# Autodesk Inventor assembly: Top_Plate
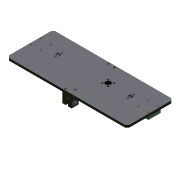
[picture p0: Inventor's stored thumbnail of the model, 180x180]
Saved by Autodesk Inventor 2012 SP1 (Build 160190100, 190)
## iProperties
Created: 2005-12
Part Number: Top_Plate
Document SubType Name: Assembly
Designer: Neil
Author: Neil
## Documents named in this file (6)
- D:\AOTC\Autodesk Inventor 2012 Essential for New Users\Autodesk Inventor 2012 Essentials - Project Files\Learning\Workspace\Sub-Assemblies\Top_Plate.iam
- D:\AOTC\Autodesk Inventor 2012 Essential for New Users\Autodesk Inventor 2012 Essentials - Project Files\Learning\Workspace\Parts\cam guide.ipt
- D:\AOTC\Autodesk Inventor 2012 Essential for New Users\Autodesk Inventor 2012 Essentials - Project Files\Learning\Workspace\Parts\AD7DE3A0-7CFF-06A5-6856-A7BB906EE278.ipt
- D:\AOTC\Autodesk Inventor 2012 Essential for New Users\Autodesk Inventor 2012 Essentials - Project Files\Learning\Workspace\Parts\TLM-2022.ipt
- D:\AOTC\Autodesk Inventor 2012 Essential for New Users\Autodesk Inventor 2012 Essentials - Project Files\Learning\Workspace\Sub-Assemblies\Pivot.iam
- D:\AOTC\Autodesk Inventor 2012 Essential for New Users\Autodesk Inventor 2012 Essentials - Project Files\Learning\Workspace\Parts\Top_Plate.ipt
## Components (8 placed, 5 different names)
1. Top_Plate:1 — Insert:1, Angle:1, Insert:2, Angle:2, Angle:3, Angle:4, Tangent:1, Mate:1, Flush:3, Tangent:2, Mate:2, Insert:6, Angle:5
2. cam guide:1 — Insert:2, Angle:2, Insert:5
3. Pivot:1 [sub-assembly] — Insert:1, Angle:1
4. Pin - Hardened Ground Production Dowel - 1/4 x 1 1/4:1 — Flush:2, Tangent:2, Mate:2
5. Pin - Hardened Ground Production Dowel - 1/4 x 1 1/4:2 — Flush:2, Tangent:1, Mate:1, Flush:3
6. Pin - Hardened Ground Production Dowel - 1/4 x 1 1/4:3 — Insert:5
7. TLM-2022:1 — Angle:3, Insert:6, Angle:5
8. TLM-2022:2 — Angle:4
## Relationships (15: Angle 5, Insert 4, Flush 2, Tangent 2, Mate 2)
- Flush:2: Pin - Hardened Ground Production Dowel - 1/4 x 1 1/4:1 ↔ Pin - Hardened Ground Production Dowel - 1/4 x 1 1/4:2
- Insert:1: Top_Plate:1 ↔ Pivot:1
- Angle:1: Top_Plate:1 ↔ Pivot:1
- Insert:2: Top_Plate:1 ↔ cam guide:1
- Angle:2: Top_Plate:1 ↔ cam guide:1
- Angle:3: Top_Plate:1 ↔ TLM-2022:1
- Angle:4: Top_Plate:1 ↔ TLM-2022:2
- Tangent:1: Top_Plate:1 ↔ Pin - Hardened Ground Production Dowel - 1/4 x 1 1/4:2
- Mate:1: Top_Plate:1 ↔ Pin - Hardened Ground Production Dowel - 1/4 x 1 1/4:2
- Flush:3: Top_Plate:1 ↔ Pin - Hardened Ground Production Dowel - 1/4 x 1 1/4:2
- Tangent:2: Top_Plate:1 ↔ Pin - Hardened Ground Production Dowel - 1/4 x 1 1/4:1
- Mate:2: Top_Plate:1 ↔ Pin - Hardened Ground Production Dowel - 1/4 x 1 1/4:1
- Insert:5: cam guide:1 ↔ Pin - Hardened Ground Production Dowel - 1/4 x 1 1/4:3
- Insert:6: Top_Plate:1 ↔ TLM-2022:1
- Angle:5: Top_Plate:1 ↔ TLM-2022:1
